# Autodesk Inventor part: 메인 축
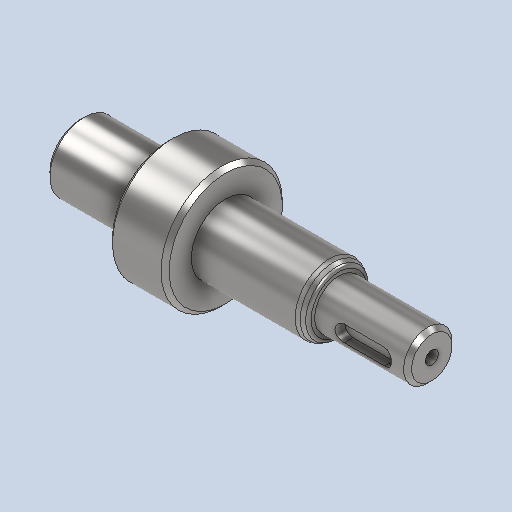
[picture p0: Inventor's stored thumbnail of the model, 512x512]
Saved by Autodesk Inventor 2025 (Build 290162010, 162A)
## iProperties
Created: 2024-07
Part Number: 메인 축
Material: 강철, 연강
Document SubType Name: Modeling
Designer: 학생
Density: 7.86 g/cm^3
Appearance: 기본값
Author: jhkim
Revision Number: 1
Sending System: Autodesk Inventor 2025
Preprocessor: ST-DEVELOPER v20
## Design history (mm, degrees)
feature "솔리드1"
node "솔리드2"
